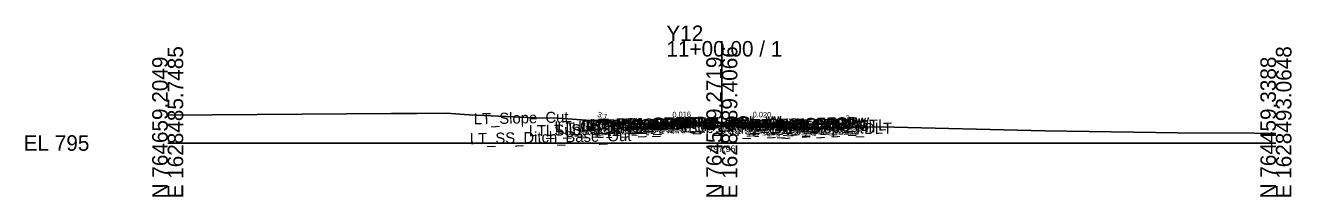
# Model space of a CAD drawing. Extents: x -26 to 203, y -10 to 3521.
# Drawn here: x -25.7 to 202.8, y 1990.3 to 2021.3 of the extents above; entities that cross this region are included whole.
import ezdxf

# ---------------------------------------------------------------- set-up
doc = ezdxf.new("R2010")
doc.units = 0
for name, color, linetype in [('Default', 7, 'Continuous'), ('Exist Cross Section Cell', 7, 'Continuous'), ('Exist XS Center Line Elevation Label', 7, 'Continuous'), ('Exist XS Ground Line', 7, 'Continuous'), ('Prop CMT Conc Surface', 7, 'Continuous'), ('Prop CMT Concrete Structures', 7, 'Continuous'), ('Prop CMT Pvmt Course 1', 7, 'Continuous'), ('Prop CMT Pvmt Course 1 Wedge', 7, 'Continuous'), ('Prop CMT Pvmt Course 2', 7, 'Continuous'), ('Prop CMT Pvmt Course 2 Wedge', 7, 'Continuous'), ('Prop CMT Pvmt Course 3', 7, 'Continuous'), ('Prop CMT Pvmt Course 3 Wedge', 7, 'Continuous'), ('Prop CMT Pvmt Surface', 7, 'Continuous'), ('Prop CMT Pvmt Wedge Surface 1', 7, 'Continuous'), ('Prop CMT Pvmt Wedge Surface 2', 7, 'Continuous'), ('Prop CMT Pvmt Wedge Surface 3', 7, 'Continuous'), ('Prop CMT Shld Paved Course 3', 7, 'Continuous'), ('Prop CMT Slope Grass', 7, 'Continuous'), ('Prop CMT Subgrade Earthwork', 7, 'Continuous'), ('Prop XS SE Text', 7, 'Continuous'), ('Prop XS Side Slope Text', 7, 'Continuous'), ('Scratch_Level_0', 7, 'Continuous')]:
    doc.layers.add(name, color=color, linetype=linetype)

msp = doc.modelspace()

# ---------------------------------------------------------------- linework, layer by layer
at = {"layer": 'Exist Cross Section Cell'}
for p, q in [((100, 2000), (100, 2018.42)), ((0, 2000), (100, 2000)), ((100, 2000), (200, 2000))]:
    msp.add_line(p, q, dxfattribs=at)
at = {"layer": 'Exist XS Ground Line'}
msp.add_lwpolyline([(0, 2005.01), (40.35, 2005.33), (44.95, 2005.31), (50.28, 2005.37), (54.43, 2005.09), (66.32, 2004.53), (70.45, 2004.47), (81.34, 2003.69), (86.66, 2003.22), (100, 2002.96), (112.41, 2002.72), (113.49, 2002.7), (113.9, 2002.69), (128.63, 2002.94), (158.31, 2002.21), (182.27, 2001.87), (196.09, 2001.81), (200, 2001.74)], dxfattribs=at)
at = {"layer": 'Prop CMT Conc Surface'}
for points in [[(85.45, 2003.54), (84.45, 2003.45), (83.45, 2003.54)], [(114.58, 2003.48), (115.58, 2003.39), (116.58, 2003.48)]]:
    msp.add_lwpolyline(points, dxfattribs=at)
at = {"layer": 'Prop CMT Concrete Structures'}
for points in [[(85.45, 2003.54), (84.45, 2003.45), (83.45, 2003.54)], [(83.45, 2003.54), (83.45, 2002.95), (85.45, 2002.95)], [(85.45, 2002.95), (85.45, 2003.54)], [(114.58, 2003.48), (115.58, 2003.39), (116.58, 2003.48)], [(116.58, 2003.48), (116.58, 2002.89), (114.58, 2002.89)], [(114.58, 2002.89), (114.58, 2003.48)]]:
    msp.add_lwpolyline(points, dxfattribs=at)
at = {"layer": 'Prop CMT Pvmt Course 1'}
for points in [[(100, 2003.77), (85.45, 2003.54)], [(85.45, 2003.54), (85.45, 2003.29)], [(85.45, 2003.29), (100, 2003.52)], [(100, 2003.77), (86.66, 2003.56)], [(86.66, 2003.43), (100, 2003.64)], [(86.66, 2003.56), (86.66, 2003.43)], [(100, 2003.64), (100, 2003.77)], [(100, 2003.52), (100, 2003.77)], [(100, 2003.77), (113.58, 2003.5)], [(100, 2003.64), (100, 2003.77)], [(100, 2003.77), (114.58, 2003.48)], [(100, 2003.52), (100, 2003.77)], [(113.58, 2003.37), (100, 2003.64)], [(114.58, 2003.23), (100, 2003.52)], [(113.58, 2003.5), (113.58, 2003.37)], [(114.58, 2003.48), (114.58, 2003.23)]]:
    msp.add_lwpolyline(points, dxfattribs=at)
at = {"layer": 'Prop CMT Pvmt Course 1 Wedge'}
for points in [[(86.66, 2003.43), (100, 2003.64)], [(100, 2003.52), (86.66, 2003.31)], [(86.66, 2003.31), (86.66, 2003.43)], [(100, 2003.64), (100, 2003.52)], [(100, 2003.64), (112.41, 2003.4), (113.49, 2003.37), (113.58, 2003.37)], [(100, 2003.52), (100, 2003.64)], [(113.58, 2003.25), (113.49, 2003.25), (112.41, 2003.27), (100, 2003.52)], [(113.58, 2003.37), (113.58, 2003.25)]]:
    msp.add_lwpolyline(points, dxfattribs=at)
at = {"layer": 'Prop CMT Pvmt Course 2'}
for points in [[(100, 2003.52), (85.45, 2003.29)], [(85.45, 2003.29), (85.45, 2002.95)], [(85.45, 2002.95), (100, 2003.19)], [(100, 2003.19), (100, 2003.52)], [(100, 2003.19), (100, 2003.52)], [(100, 2003.52), (114.58, 2003.23)], [(114.58, 2002.89), (100, 2003.19)], [(114.58, 2003.23), (114.58, 2002.89)]]:
    msp.add_lwpolyline(points, dxfattribs=at)
at = {"layer": 'Prop CMT Pvmt Course 2 Wedge'}
for points in [[(86.66, 2003.31), (100, 2003.52)], [(86.66, 2003.22), (86.66, 2003.31)], [(100, 2003.19), (93.68, 2003.08), (86.66, 2003.22)], [(100, 2003.52), (100, 2003.19)], [(100, 2003.52), (112.41, 2003.27), (113.49, 2003.25), (113.58, 2003.25)], [(100, 2003.19), (100, 2003.52)], [(113.58, 2002.91), (113.49, 2002.92), (112.41, 2002.94), (100, 2003.19)], [(113.58, 2003.25), (113.58, 2002.91)]]:
    msp.add_lwpolyline(points, dxfattribs=at)
at = {"layer": 'Prop CMT Pvmt Course 3'}
msp.add_line((116.58, 2002.89), (117.08, 2002.89), dxfattribs=at)
for points in [[(100, 2003.19), (85.45, 2002.95)], [(85.45, 2002.95), (85.45, 2002.62)], [(85.45, 2002.62), (86.66, 2002.64)], [(100, 2002.85), (100, 2003.19)], [(100, 2003.19), (114.58, 2002.89)], [(100, 2002.85), (100, 2003.19)], [(114.58, 2002.56), (113.58, 2002.58)], [(114.58, 2002.89), (114.58, 2002.56)]]:
    msp.add_lwpolyline(points, dxfattribs=at)
at = {"layer": 'Prop CMT Pvmt Course 3 Wedge'}
for points in [[(93.68, 2003.08), (100, 2003.19)], [(100, 2002.96), (93.68, 2003.08)], [(100, 2003.19), (100, 2002.96)], [(100, 2003.19), (112.41, 2002.94), (113.49, 2002.92), (113.58, 2002.91)], [(100, 2002.96), (100, 2003.19)], [(113.58, 2002.69), (113.49, 2002.7), (112.41, 2002.72), (100, 2002.96)], [(113.58, 2002.91), (113.58, 2002.69)]]:
    msp.add_lwpolyline(points, dxfattribs=at)
at = {"layer": 'Prop CMT Pvmt Surface'}
for points in [[(100, 2003.77), (85.45, 2003.54)], [(100, 2003.77), (86.66, 2003.56)], [(100, 2003.77), (114.58, 2003.48)], [(100, 2003.77), (113.58, 2003.5)]]:
    msp.add_lwpolyline(points, dxfattribs=at)
at = {"layer": 'Prop CMT Pvmt Wedge Surface 1'}
for points in [[(85.45, 2003.29), (85.45, 2003.54)], [(100, 2003.64), (86.66, 2003.43)], [(86.66, 2003.43), (86.66, 2003.56)], [(100, 2003.64), (113.58, 2003.37)], [(113.58, 2003.37), (113.58, 2003.5)], [(114.58, 2003.23), (114.58, 2003.48)]]:
    msp.add_lwpolyline(points, dxfattribs=at)
at = {"layer": 'Prop CMT Pvmt Wedge Surface 2'}
for points in [[(85.45, 2003.29), (85.45, 2003.54)], [(86.66, 2003.31), (86.66, 2003.56)], [(100, 2003.52), (86.66, 2003.31)], [(100, 2003.52), (100, 2003.77)], [(100, 2003.52), (100, 2003.77)], [(100, 2003.52), (100, 2003.77)], [(100, 2003.52), (100, 2003.77)], [(100, 2003.52), (113.58, 2003.25)], [(113.58, 2003.25), (113.58, 2003.5)], [(114.58, 2003.23), (114.58, 2003.48)]]:
    msp.add_lwpolyline(points, dxfattribs=at)
at = {"layer": 'Prop CMT Pvmt Wedge Surface 3'}
for points in [[(85.45, 2002.95), (85.45, 2003.54)], [(86.66, 2002.97), (86.66, 2003.56)], [(100, 2003.19), (86.66, 2002.97)], [(100, 2003.19), (100, 2003.77)], [(100, 2003.19), (100, 2003.77)], [(100, 2003.19), (100, 2003.77)], [(100, 2003.19), (100, 2003.77)], [(100, 2003.19), (113.58, 2002.91)], [(113.58, 2002.91), (113.58, 2003.5)], [(114.58, 2002.89), (114.58, 2003.48)]]:
    msp.add_lwpolyline(points, dxfattribs=at)
at = {"layer": 'Prop CMT Shld Paved Course 3'}
for p, q in [((82.61, 2002.61), (85.45, 2002.62)), ((117.42, 2002.55), (114.58, 2002.56))]:
    msp.add_line(p, q, dxfattribs=at)
for points in [[(85.45, 2002.95), (83.45, 2002.95), (82.95, 2002.95), (82.61, 2002.61)], [(114.58, 2002.89), (117.08, 2002.89), (117.08, 2002.89), (117.42, 2002.55)]]:
    msp.add_lwpolyline(points, dxfattribs=at)
at = {"layer": 'Prop CMT Slope Grass'}
for points in [[(83.45, 2003.54), (78.45, 2003.64), (77.46, 2003.97)], [(116.58, 2003.48), (121.58, 2003.58), (123.74, 2002.85)]]:
    msp.add_lwpolyline(points, dxfattribs=at)
at = {"layer": 'Prop CMT Subgrade Earthwork'}
for p, q in [((82.61, 2002.61), (81.65, 2003.57)), ((85.45, 2002.62), (82.61, 2002.61)), ((114.58, 2002.56), (117.42, 2002.55)), ((117.42, 2002.55), (118.38, 2003.51))]:
    msp.add_line(p, q, dxfattribs=at)
for points in [[(86.66, 2002.64), (85.45, 2002.62)], [(86.66, 2002.64), (86.67, 2003.22)], [(113.58, 2002.58), (113.57, 2002.69)], [(113.58, 2002.58), (114.58, 2002.56)]]:
    msp.add_lwpolyline(points, dxfattribs=at)

# ---------------------------------------------------------------- texts
at = {"layer": 'Default'}
msp.add_text('-', height=0.0001, dxfattribs=at).set_placement((0, 2000))
at = {"layer": 'Exist Cross Section Cell'}
for s, p in [('Y12', (90, 2018.42)), ('11+00.00 / 1', (90, 2015.62)), ('EL 795', (-26, 1998.6))]:
    msp.add_text(s, height=2.8, dxfattribs=at).set_placement(p)
for s, p in [('E 1628485.7485', (2.8, 1990)), ('E 1628489.4066', (102.8, 1990)), ('E 1628493.0648', (202.8, 1990)), ('N 764659.2049', (0, 1990)), ('N 764559.2719', (100, 1990)), ('N 764459.3388', (200, 1990))]:
    msp.add_text(s, height=2.8, rotation=90, dxfattribs=at).set_placement(p)
at = {"layer": 'Exist XS Center Line Elevation Label'}
msp.add_text('797.96', height=1.2, dxfattribs=at).set_placement((97.56, 1998.36))
at = {"layer": 'Prop XS SE Text'}
for s, rotation, p in [('0.016', 0.9099, (91.09, 2004.63)), ('0.020', 358.8542, (105.56, 2004.66))]:
    msp.add_text(s, height=1, rotation=rotation, dxfattribs=at).set_placement(p)
at = {"layer": 'Prop XS Side Slope Text'}
for p in [(77.44, 2004.77), (122.14, 2004.18)]:
    msp.add_text('3:1', height=1, rotation=341.5651, dxfattribs=at).set_placement(p)
at = {"layer": 'Scratch_Level_0'}
for s, p in [('LT_Slope_Cut', (55.25, 2003.36)), ('LT_GS_OS_CTL', (69.84, 2001.93)), ('LT_PV2_OEEOP_W', (74.1, 2002.06)), ('LT_PV1_OEEOP_W', (74.67, 2002.19)), ('LT_PS2_OEOP', (75.45, 2002.09)), ('LT_PV2_OEOT', (75.65, 2002.09)), ('LT_PV1_OEOT', (76.21, 2002.35)), ('LT_PS1_OEOP', (76.28, 2002.35)), ('LT_PV1_OEEOP', (76.56, 2002.35)), ('RT_PV1_PGL_W', (89.86, 2002.44)), ('LT_PV1_PGL_W', (89.91, 2002.44)), ('PV2_PGL', (93.93, 2002.4)), ('PV3_PGL', (93.93, 2002.06)), ('PV1_PGL', (94.49, 2002.66)), ('RT_PV2_OEEOP_W', (100.97, 2001.99)), ('RT_PV1_OEEOP_W', (101.53, 2002.13)), ('RT_PV1_OEEOP', (103.42, 2002.29)), ('RT_PV2_OEOT', (104.72, 2002.03)), ('RT_PS2_OEOP', (105.04, 2002.03)), ('RT_PV1_OEOT', (105.29, 2002.29)), ('RT_PS1_OEOP', (105.35, 2002.29)), ('RT_GS_OS_CTL', (108.92, 2001.86)), ('LT_SS_Ditch_Base_Out', (54.55, 1999.78)), ('LT_Sub_OSS_DLT', (65.19, 2001.22)), ('LT_Sub_Trench_Out', (68.24, 2001.28)), ('LT_PS3_Shelf_Out', (70.36, 2001.65)), ('LT_PV3_OEEOP_W', (74.1, 2001.72)), ('LT_PS3_OEOP', (75.11, 2001.75)), ('LT_Sub_OEOT', (75.55, 2001.42)), ('LT_PV3_OEOT', (75.65, 2001.76)), ('Sub_PGL', (93.83, 2001.73)), ('RT_Sub_Trench_Out', (100.19, 2001.22)), ('RT_PV3_OEEOP_W', (100.97, 2001.66)), ('RT_PS3_Shelf_Out', (101.63, 2001.59)), ('RT_Sub_OEOT', (104.63, 2001.36)), ('RT_PV3_OEOT', (104.72, 2001.7)), ('RT_PS3_OEOP', (105.38, 2001.69)), ('RT_Sub_OSS_DLT', (107.27, 2001.24)), ('RT_Slope_Fill', (110.91, 2001.61))]:
    msp.add_text(s, height=2, rotation=1.1458, dxfattribs=at).set_placement(p)

doc.saveas('drawing.dxf')
